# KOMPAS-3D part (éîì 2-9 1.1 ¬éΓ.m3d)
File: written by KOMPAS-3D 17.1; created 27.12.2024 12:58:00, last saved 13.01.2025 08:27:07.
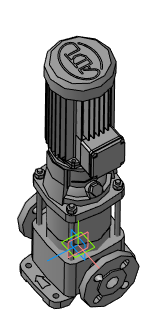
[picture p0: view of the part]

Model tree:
1. Операция без истории:3  (labels: ВМН 2-9 1.1 кВт)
